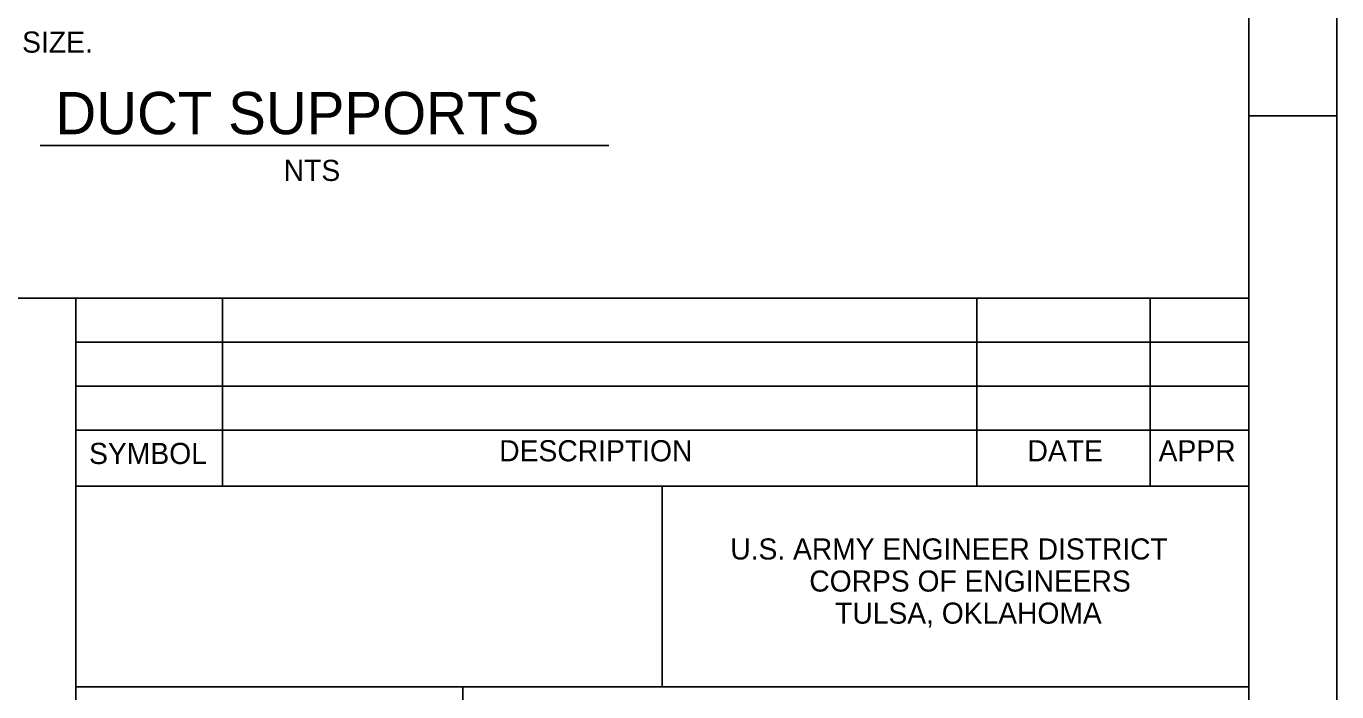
# Model space of a CAD drawing. Extents: x 9999.96 to 10005.26, y 9999.88 to 10002.38.
# Drawn here: x 10002.841 to 10003.46, y 10000.258 to 10000.572 of the extents above; entities that cross this region are included whole.
import ezdxf

# ---------------------------------------------------------------- set-up
doc = ezdxf.new("R2010")
doc.units = 0
doc.layers.add('Level 1', color=7, linetype='Continuous')
doc.layers.add('Level 2', color=7, linetype='Continuous')

msp = doc.modelspace()

# ---------------------------------------------------------------- linework, layer by layer
at = {"layer": 'Level 1'}
for p, q in [((10003.46033, 10002.38453), (10003.46033, 9999.88453)), ((10003.41867, 10002.34286), (10003.41867, 9999.9262)), ((10003.46033, 10000.53006), (10003.41898, 10000.53006)), ((10002.86401, 10000.44391), (10002.86401, 10000.35495)), ((10003.41867, 10000.44391), (10002.86401, 10000.44391)), ((10002.93333, 10000.44391), (10002.93333, 10000.35536)), ((10003.29017, 10000.44391), (10003.29017, 10000.35536)), ((10003.37208, 10000.44391), (10003.37208, 10000.35536)), ((10003.41867, 10000.42307), (10002.86401, 10000.42307)), ((10002.86401, 10000.40224), (10003.41867, 10000.40224)), ((10002.86401, 10000.38141), (10003.41867, 10000.38141)), ((10002.86401, 9999.92827), (10002.86401, 10000.35495)), ((10003.41867, 10000.35495), (10002.86401, 10000.35495)), ((10003.14133, 10000.26011), (10003.14133, 10000.35495)), ((10002.86401, 10000.26011), (10003.41867, 10000.26011)), ((10003.04708, 10000.26011), (10003.04708, 9999.9945))]:
    msp.add_line(p, q, dxfattribs=at)
at = {"layer": 'Level 2'}
for p, q in [((10002.84711, 10000.51611), (10003.11614, 10000.51611)), ((10002.54716, 10000.44391), (10002.86401, 10000.44391))]:
    msp.add_line(p, q, dxfattribs=at)

# ---------------------------------------------------------------- texts
at = {"layer": 'Level 1'}
for s, height, p in [('SYMBOL', 0.01, (10002.8703, 10000.36547)), ('DESCRIPTION', 0.01, (10003.06425, 10000.36674)), ('DATE', 0.01, (10003.31408, 10000.36674)), ('APPR', 0.01, (10003.37608, 10000.36674)), ('U.S. ARMY ENGINEER DISTRICT', 0.0099792, (10003.17354, 10000.32032)), ('CORPS OF ENGINEERS', 0.0099792, (10003.2109, 10000.30516)), ('TULSA, OKLAHOMA', 0.0099792, (10003.22311, 10000.28999))]:
    msp.add_text(s, height=height, dxfattribs=at).set_placement(p)
at = {"layer": 'Level 2'}
for s, height, p in [('   AND GREATER DUCT SIZE.', 0.01, (10002.68633, 10000.55995)), ('DUCT SUPPORTS', 0.02, (10002.85436, 10000.52138)), ('NTS', 0.01, (10002.96232, 10000.4993))]:
    msp.add_text(s, height=height, dxfattribs=at).set_placement(p)

doc.saveas('drawing.dxf')
